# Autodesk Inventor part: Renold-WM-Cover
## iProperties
Author: Administrator
Shininess: 61.0
Angle Display Precision: 2
Document Length Units: 11272
Document Angle Units: 11286
Document Time Units: 11279
Document Mass Units: 11290
Document Length Units Precision: 3
Document Angle Units Precision: 2
Compacted: True
PropertySet Name: _Private Model Information
Created: 2002-04
Part Number: Renold-WM-Cover
Material: ASTM A36 HRS
Document SubType Name: Modeling
Designer: Administrator
Control State: 0
Master: False
Checked Out: False
PropertySet Name: Design Tracking Control
Density: 0.0
Volumn: 0.0
Area: 0.0
PropertySet Name: Model Information
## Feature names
1. body [Extrusion]
2. Fillet1
3. Shell1
4. bolt_holes [Extrusion]
